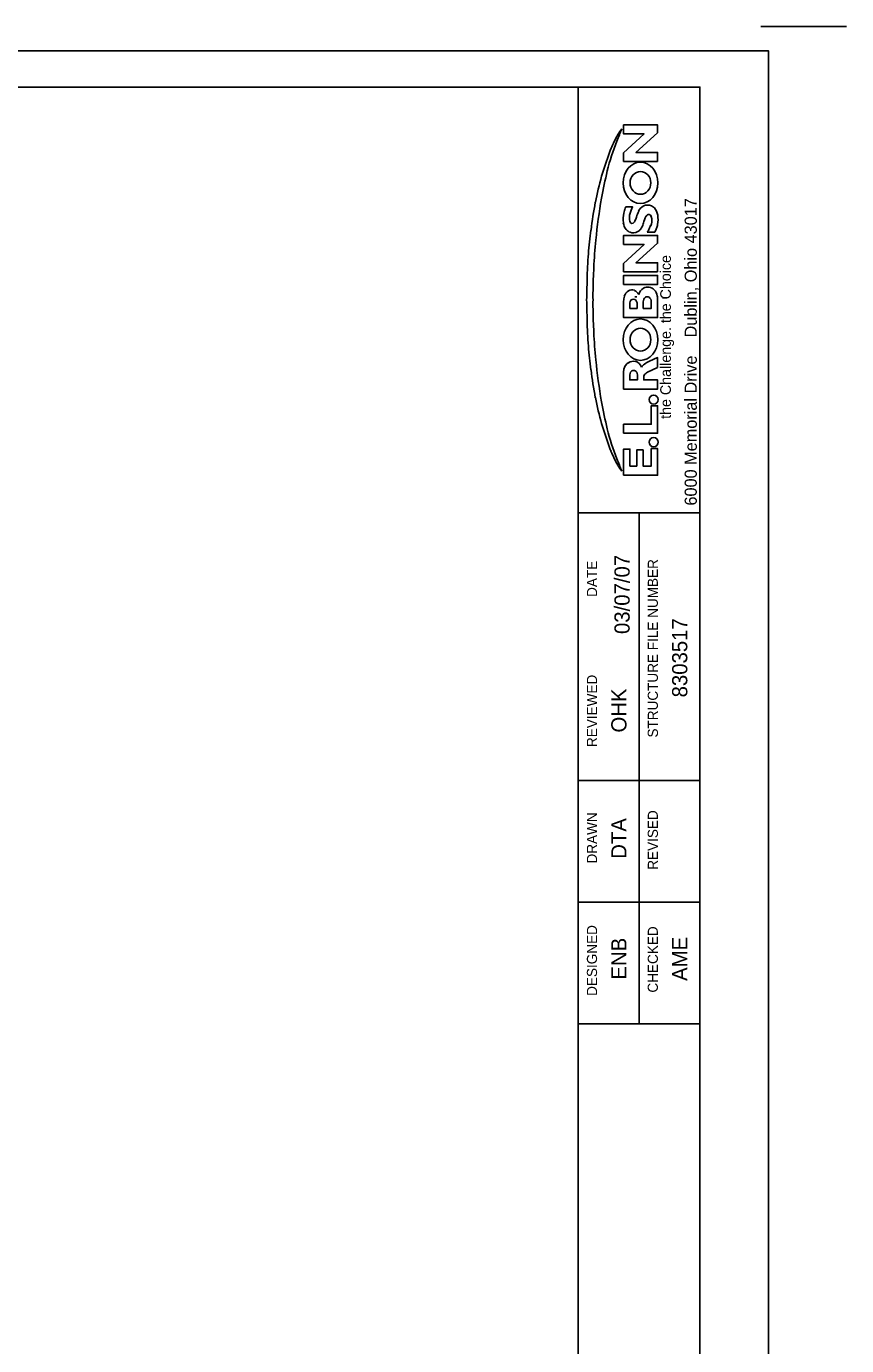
# Model space of a CAD drawing. Extents: x -9.2 to 26.7, y -24.6 to -2.6.
# Drawn here: x 20 to 26.74, y -13.46 to -2.61 of the extents above; entities that cross this region are included whole.
import ezdxf

# ---------------------------------------------------------------- set-up
doc = ezdxf.new("R2010")
doc.units = 0
for name, color, linetype in [('Default', 7, 'Continuous'), ('SH_Border', 7, 'Continuous'), ('SH_Cut_Line', 7, 'Continuous'), ('SH_Data', 7, 'Continuous')]:
    doc.layers.add(name, color=color, linetype=linetype)

msp = doc.modelspace()

# ---------------------------------------------------------------- linework, layer by layer
at = {"layer": 'Default'}
for p, q in [((25.163, -4.303), (25.101, -4.303)), ((25.101, -4.303), (25.163, -4.303)), ((24.906, -5.006), (24.906, -4.871)), ((25.185, -4.856), (25.185, -5.006)), ((24.958, -4.886), (24.958, -4.931)), ((24.958, -4.931), (24.958, -4.886)), ((25.185, -5.006), (24.906, -5.006)), ((25.185, -5.416), (25.104, -5.456)), ((25.104, -5.456), (25.185, -5.416)), ((24.957, -5.477), (24.957, -5.519)), ((24.957, -5.519), (24.957, -5.477)), ((24.957, -5.519), (25.02, -5.519)), ((25.02, -5.519), (24.957, -5.519)), ((25.02, -5.519), (25.02, -5.477)), ((25.02, -5.477), (25.02, -5.519))]:
    msp.add_line(p, q, dxfattribs=at)
for points in [[(25.185, -3.722), (24.906, -3.722), (24.906, -3.653), (25.075, -3.497), (24.906, -3.497), (24.906, -3.423), (25.185, -3.423), (25.185, -3.487), (25.008, -3.648), (25.185, -3.648)], [(25.185, -4.63), (24.906, -4.63), (24.906, -4.561), (25.075, -4.405), (24.906, -4.405), (24.906, -4.331), (25.185, -4.331), (25.185, -4.395), (25.008, -4.556), (25.185, -4.556)], [(24.906, -4.734), (24.906, -4.66), (25.185, -4.66), (25.185, -4.734)], [(24.906, -6.302), (24.906, -6.087), (24.958, -6.087), (24.958, -6.227), (25.015, -6.227), (25.015, -6.095), (25.067, -6.095), (25.067, -6.227), (25.134, -6.227), (25.134, -6.084), (25.185, -6.084), (25.185, -6.302)]]:
    msp.add_lwpolyline(points, close=True, dxfattribs=at)
for points in [[(24.924, -4.096), (24.98, -4.096), (24.969, -4.122)], [(24.969, -4.122), (24.98, -4.096), (24.924, -4.096)], [(25.185, -4.856), (25.185, -5.006), (24.906, -5.006), (24.906, -4.871)], [(24.906, -4.871), (24.906, -5.006), (25.185, -5.006)], [(25.068, -4.877), (25.068, -4.931), (25.133, -4.931), (25.133, -4.877)], [(25.133, -4.877), (25.133, -4.931), (25.068, -4.931), (25.068, -4.877)], [(25.185, -5.006), (25.185, -4.856)], [(24.958, -4.931), (25.017, -4.931), (25.017, -4.886)], [(25.017, -4.886), (25.017, -4.931), (24.958, -4.931)], [(25.12, -5.366), (25.185, -5.335), (25.185, -5.416)], [(25.185, -5.416), (25.185, -5.335), (25.12, -5.366)], [(25.072, -5.498), (25.072, -5.519), (25.185, -5.519), (25.185, -5.594), (24.906, -5.594), (24.906, -5.519), (24.906, -5.455)], [(24.906, -5.455), (24.906, -5.519), (24.906, -5.594), (25.185, -5.594)], [(24.957, -5.477), (24.957, -5.519), (25.02, -5.519), (25.02, -5.477)], [(25.185, -5.594), (25.185, -5.519), (25.072, -5.519), (25.072, -5.498)], [(24.906, -5.958), (24.906, -5.883), (25.134, -5.883), (25.134, -5.731), (25.185, -5.731), (25.185, -5.958), (24.906, -5.958)], [(25.185, -5.731), (25.134, -5.731), (25.134, -5.883), (24.906, -5.883), (24.906, -5.958)], [(24.906, -5.958), (25.185, -5.958), (25.185, -5.731)]]:
    msp.add_lwpolyline(points, dxfattribs=at)
for centre, major_axis, ratio, start_param, end_param in [((-13.595, 17.645), (0, 49.953), 0.85, 4.274094, 4.276309), ((-13.595, 17.645), (0, 49.953), 0.85, 4.274094, 4.276309), ((25.117, -3.701), (0, 0.363), 0.85, 0.822588, 0.988431), ((25.117, -3.701), (0, 0.363), 0.85, 0.822588, 0.988431), ((26.148, -4.27), (0, 1.685), 0.85, 1.132502, 1.288747), ((26.148, -4.27), (0, 1.685), 0.85, 1.132502, 1.288747), ((25.669, -4.13), (0, 1.141), 0.85, 0.988431, 1.105191), ((25.669, -4.13), (0, 1.141), 0.85, 0.988431, 1.105191), ((27.222, -4.875), (0, 3.112), 0.85, 1.165908, 1.233316), ((27.222, -4.875), (0, 3.112), 0.85, 1.165908, 1.233316), ((25.246, -3.879), (0, 0.583), 0.85, 1.105191, 1.165908), ((25.246, -3.879), (0, 0.583), 0.85, 1.105191, 1.165908), ((26.431, -4.527), (0, 2.119), 0.85, 1.243005, 1.347881), ((26.431, -4.527), (0, 2.119), 0.85, 1.243005, 1.347881), ((27.646, -4.781), (0, 3.52), 0.85, 1.288747, 1.354281), ((27.646, -4.781), (0, 3.52), 0.85, 1.288747, 1.354281), ((25.045, -3.899), (0, -0.0938), 0.910305, 4.71238898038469, 4.712389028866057), ((27.62, -4.797), (0, 3.544), 0.85, 1.360764, 1.426378), ((27.62, -4.797), (0, 3.544), 0.85, 1.360764, 1.426378), ((28.865, -4.975), (0, 4.963), 0.85, 1.378198, 1.448475), ((28.865, -4.975), (0, 4.963), 0.85, 1.378198, 1.448475), ((25.077, -4.199), (0, 0.206), 0.85, 1.108668, 1.320154), ((25.077, -4.199), (0, 0.206), 0.85, 1.108668, 1.320154), ((24.786, -4.029), (0, 0.176), 0.85, 4.250261, 4.3216), ((24.786, -4.029), (0, 0.176), 0.85, 4.250261, 4.3216), ((25.11, -4.188), (0, 0.11), 0.85, 0.486829, 1.030221), ((25.11, -4.188), (0, 0.11), 0.85, 0.486829, 1.030221), ((25.045, -3.899), (0, -0.17), 0.841969, 0, 4.84813681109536e-08), ((25.097, -4.158), (0, 0.0761), 0.85, 0.083326, 0.486829), ((25.097, -4.158), (0, 0.0761), 0.85, 0.083326, 0.486829), ((25.102, -4.236), (0, 0.154), 0.85, 6.083659, 6.366511), ((25.102, -4.236), (0, 0.154), 0.85, 6.083659, 6.366511), ((25.116, -4.158), (0, 0.0741), 0.85, 5.529173, 6.083659), ((25.116, -4.158), (0, 0.0741), 0.85, 5.529173, 6.083659), ((25.096, -4.183), (0, 0.109), 0.85, 4.887723, 5.529173), ((25.096, -4.183), (0, 0.109), 0.85, 4.887723, 5.529174), ((25.064, -4.195), (0, 0.19), 0.85, 1.320154, 1.737094), ((25.064, -4.195), (0, 0.19), 0.85, 1.320154, 1.737094), ((24.996, -4.208), (0, 0.11), 0.85, 1.737094, 2.325359), ((24.996, -4.208), (0, 0.11), 0.85, 1.737094, 2.325359), ((25.049, -4.186), (0, 0.111), 0.85, 1.456901, 1.818883), ((25.049, -4.186), (0, 0.111), 0.85, 1.456901, 1.818883), ((25.052, -4.187), (0, 0.115), 0.85, 1.297264, 1.456901), ((25.052, -4.187), (0, 0.115), 0.85, 1.297264, 1.456901), ((24.98, -4.207), (0, 0.0279), 0.85, 1.818883, 2.384672), ((24.98, -4.207), (0, 0.0279), 0.85, 1.818883, 2.384672), ((25.118, -4.209), (0, 0.196), 0.85, 1.114999, 1.297264), ((25.118, -4.209), (0, 0.196), 0.85, 1.114999, 1.297264), ((24.975, -4.213), (0, 0.0197), 0.85, 2.384672, 3.137191), ((24.975, -4.213), (0, 0.0197), 0.85, 2.384672, 3.137191), ((24.975, -4.205), (0, 0.0276), 0.85, 3.137191, 4.01614), ((24.975, -4.205), (0, 0.0276), 0.85, 3.137191, 4.01614), ((24.947, -4.177), (0, 0.071), 0.85, 4.01614, 4.175459), ((24.947, -4.177), (0, 0.071), 0.85, 4.01614, 4.175459), ((24.878, -4.129), (0, 0.165), 0.85, 4.175459, 4.396402), ((24.878, -4.129), (0, 0.165), 0.85, 4.175459, 4.396402), ((25.204, -4.254), (0, 0.238), 0.85, 1.030221, 1.254809), ((25.204, -4.254), (0, 0.238), 0.85, 1.030221, 1.254809), ((25.687, -4.508), (0, 0.778), 0.85, 1.164639, 1.211778), ((25.687, -4.508), (0, 0.778), 0.85, 1.164639, 1.211778), ((25.301, -4.312), (0, 0.284), 0.85, 1.063855, 1.164639), ((25.301, -4.312), (0, 0.284), 0.85, 1.063855, 1.164639), ((25.113, -4.19), (0, 0.0304), 0.85, 0.715581, 1.063855), ((25.113, -4.19), (0, 0.0304), 0.85, 0.715581, 1.063855), ((25.114, -4.191), (0, 0.0317), 0.85, 0.212074, 0.715581), ((25.114, -4.191), (0, 0.0317), 0.85, 0.212074, 0.715581), ((25.113, -4.185), (0, 0.026), 0.85, 5.247627, 6.495259), ((25.113, -4.185), (0, 0.026), 0.85, 5.247627, 6.495259), ((25.051, -4.205), (0, 0.103), 0.85, 4.251833, 4.86616), ((25.051, -4.205), (0, 0.103), 0.85, 4.251833, 4.86616), ((25.096, -4.196), (0, 0.0483), 0.85, 4.86616, 5.247627), ((25.096, -4.196), (0, 0.0483), 0.85, 4.86616, 5.247627), ((25.015, -4.2), (0, 0.205), 0.85, 4.51081, 4.887723), ((25.015, -4.2), (0, 0.205), 0.85, 4.51081, 4.887723), ((26.199, -4.62), (0, 1.866), 0.85, 1.391456, 1.496401), ((26.199, -4.62), (0, 1.866), 0.85, 1.391456, 1.496401), ((24.976, -4.231), (0, 0.0764), 0.85, 2.325359, 2.878408), ((24.976, -4.231), (0, 0.0764), 0.85, 2.325359, 2.878408), ((24.984, -4.196), (0, 0.113), 0.85, 2.878408, 3.55749), ((24.984, -4.196), (0, 0.113), 0.85, 2.878408, 3.55749), ((24.997, -4.232), (0, 0.0738), 0.85, 3.55749, 3.971659), ((24.997, -4.232), (0, 0.0738), 0.85, 3.55749, 3.971659), ((24.953, -4.184), (0, 0.145), 0.85, 3.971659, 4.353371), ((24.953, -4.184), (0, 0.145), 0.85, 3.971659, 4.353371), ((24.924, -4.14), (0, 0.265), 0.85, 4.050165, 4.172563), ((24.924, -4.14), (0, 0.265), 0.85, 4.050165, 4.172563), ((24.847, -4.086), (0, 0.37), 0.85, 4.172563, 4.251833), ((24.847, -4.086), (0, 0.37), 0.85, 4.172563, 4.251833), ((25.058, -4.214), (0, 0.152), 0.85, 4.087438, 4.318356), ((25.058, -4.214), (0, 0.152), 0.85, 4.087438, 4.318356), ((25.042, -4.206), (0, 0.173), 0.85, 4.318356, 4.51081), ((25.042, -4.206), (0, 0.173), 0.85, 4.318356, 4.51081), ((30.463, -5.041), (0, 6.84), 0.85, 1.472392, 1.505619), ((30.463, -5.041), (0, 6.84), 0.85, 1.472392, 1.505619), ((26.401, -4.721), (0, 2.111), 0.85, 1.456986, 1.558686), ((26.401, -4.721), (0, 2.111), 0.85, 1.456986, 1.558686), ((28.007, -4.852), (0, 3.944), 0.85, 1.505619, 1.553601), ((28.007, -4.852), (0, 3.944), 0.85, 1.505619, 1.553601), ((28.209, -4.914), (0, 4.243), 0.85, 1.519271, 1.558345), ((28.209, -4.914), (0, 4.243), 0.85, 1.519271, 1.558345), ((25.104, -4.846), (0, 0.0906), 0.85, 0.462144, 1.247207), ((25.104, -4.846), (0, 0.0906), 0.85, 0.462144, 1.247207), ((25.104, -4.846), (0, 0.0906), 0.85, 0.462144, 1.247207), ((25.105, -4.854), (0, 0.0982), 0.85, 6.14188, 6.715345), ((25.105, -4.854), (0, 0.0982), 0.85, 6.14188, 6.715345), ((25.105, -4.854), (0, 0.0982), 0.85, 6.14188, 6.715345), ((25.109, -4.845), (0, 0.0885), 0.85, 5.535543, 6.182102), ((25.109, -4.845), (0, 0.0885), 0.85, 5.535543, 6.182102), ((25.109, -4.845), (0, 0.0885), 0.85, 5.535543, 6.182102), ((28.209, -4.809), (0, 4.243), 0.85, 1.583248, 1.622322), ((28.209, -4.809), (0, 4.243), 0.85, 1.583248, 1.622322), ((26.556, -4.823), (0, 2.237), 0.85, 1.553601, 1.587991), ((26.556, -4.823), (0, 2.237), 0.85, 1.553601, 1.587991), ((26.556, -4.9), (0, 2.237), 0.85, 1.553601, 1.587991), ((26.556, -4.9), (0, 2.237), 0.85, 1.553601, 1.587991), ((25.012, -4.873), (0, 0.124), 0.85, 1.228703, 1.558605), ((25.012, -4.873), (0, 0.124), 0.85, 1.228703, 1.558605), ((25.012, -4.873), (0, 0.124), 0.85, 1.228703, 1.558605), ((24.978, -4.862), (0, 0.0833), 0.85, 0.473795, 1.194239), ((24.978, -4.862), (0, 0.0833), 0.85, 0.473795, 1.194239), ((24.978, -4.862), (0, 0.0833), 0.85, 0.473795, 1.194239), ((24.976, -4.848), (0, 0.0696), 0.85, 5.943917, 6.808987), ((24.976, -4.848), (0, 0.0696), 0.85, 5.943917, 6.808987), ((24.976, -4.848), (0, 0.0696), 0.85, 5.943917, 6.808987), ((24.986, -4.888), (0, 0.0337), 0.85, 6.249041, 7.784024), ((24.986, -4.888), (0, 0.0337), 0.85, 6.249041, 7.784024), ((24.988, -4.888), (0, 0.0337), 0.85, 4.782347, 6.317329), ((24.988, -4.888), (0, 0.0337), 0.85, 4.782347, 6.317329), ((24.974, -4.856), (0, 0.0776), 0.85, 5.231996, 5.947796), ((24.974, -4.856), (0, 0.0776), 0.85, 5.231996, 5.947796), ((24.974, -4.856), (0, 0.0776), 0.85, 5.231996, 5.947795), ((25.102, -4.875), (0, 0.0402), 0.85, 0.503186, 1.629765), ((25.102, -4.875), (0, 0.0402), 0.85, 0.503186, 1.629765), ((25.1, -4.871), (0, 0.0358), 0.85, 6.277029, 6.794667), ((25.1, -4.871), (0, 0.0358), 0.85, 6.277029, 6.794667), ((25.101, -4.871), (0, 0.0358), 0.85, 5.771704, 6.289341), ((25.101, -4.871), (0, 0.0358), 0.85, 5.771704, 6.289341), ((25.099, -4.875), (0, 0.0402), 0.85, 4.65342, 5.779999), ((25.099, -4.875), (0, 0.0402), 0.85, 4.65342, 5.779999), ((25.114, -4.841), (0, 0.0818), 0.85, 4.885157, 5.560215), ((25.114, -4.841), (0, 0.0818), 0.85, 4.885157, 5.560215), ((25.114, -4.841), (0, 0.0818), 0.85, 4.885157, 5.560215), ((25.014, -4.864), (0, 0.202), 0.85, 4.750784, 4.89449), ((25.014, -4.864), (0, 0.202), 0.85, 4.750784, 4.89449), ((25.014, -4.864), (0, 0.202), 0.85, 4.750784, 4.89449), ((28.007, -4.871), (0, 3.944), 0.85, 1.587991, 1.635974), ((28.007, -4.871), (0, 3.944), 0.85, 1.587991, 1.635974), ((26.401, -5.002), (0, 2.111), 0.85, 1.582906, 1.684607), ((26.401, -5.002), (0, 2.111), 0.85, 1.582906, 1.684607), ((30.463, -4.682), (0, 6.84), 0.85, 1.635974, 1.669201), ((30.463, -4.682), (0, 6.84), 0.85, 1.635974, 1.669201), ((25.045, -5.188), (0, -0.0938), 0.910305, 4.71238898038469, 4.712389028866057), ((26.199, -5.103), (0, 1.866), 0.85, 1.645192, 1.750137), ((26.199, -5.103), (0, 1.866), 0.85, 1.645192, 1.750137), ((28.865, -4.748), (0, 4.963), 0.85, 1.693118, 1.763395), ((28.865, -4.748), (0, 4.963), 0.85, 1.693118, 1.763395), ((24.982, -5.456), (0, 0.0895), 0.85, 0.482355, 1.561069), ((24.982, -5.456), (0, 0.0895), 0.85, 0.482355, 1.561069), ((24.988, -5.465), (0, 0.1), 0.85, 6.102437, 6.781247), ((24.988, -5.465), (0, 0.1), 0.85, 6.102437, 6.781247), ((24.987, -5.452), (0, 0.0881), 0.85, 5.152888, 6.061538), ((24.987, -5.452), (0, 0.0881), 0.85, 5.152888, 6.061538), ((25.045, -5.188), (0, -0.17), 0.841969, 0, 4.84813681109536e-08), ((25.104, -5.451), (0, 0.069), 0.85, 0.463729, 1.012038), ((25.104, -5.451), (0, 0.069), 0.85, 0.463729, 1.012038), ((25.211, -5.663), (0, 0.316), 0.85, 0.346308, 0.520291), ((25.211, -5.663), (0, 0.316), 0.85, 0.346308, 0.520291), ((27.62, -4.926), (0, 3.544), 0.85, 1.715214, 1.780828), ((27.62, -4.926), (0, 3.544), 0.85, 1.715214, 1.780828), ((24.997, -5.48), (0, 0.0467), 0.85, 1.002734, 1.50285), ((24.997, -5.48), (0, 0.0467), 0.85, 1.002734, 1.50285), ((24.997, -5.48), (0, 0.0467), 0.85, 1.002734, 1.50285), ((24.988, -5.477), (0, 0.0365), 0.85, 6.259044, 7.205975), ((24.988, -5.477), (0, 0.0365), 0.85, 6.259044, 7.205975), ((24.988, -5.477), (0, 0.0365), 0.85, 6.259044, 7.205975), ((24.989, -5.477), (0, 0.0365), 0.85, 5.360396, 6.307326), ((24.989, -5.477), (0, 0.0365), 0.85, 5.360396, 6.307326), ((24.989, -5.477), (0, 0.0365), 0.85, 5.360396, 6.307326), ((24.981, -5.48), (0, 0.0467), 0.85, 4.780335, 5.280452), ((24.981, -5.48), (0, 0.0467), 0.85, 4.780335, 5.280452), ((24.981, -5.48), (0, 0.0467), 0.85, 4.780335, 5.280452), ((25.098, -5.497), (0, 0.0303), 0.85, 0.984544, 1.600686), ((25.098, -5.497), (0, 0.0303), 0.85, 0.984544, 1.600686), ((25.121, -5.517), (0, 0.0643), 0.85, 0.32473, 0.965239), ((25.121, -5.517), (0, 0.0643), 0.85, 0.32473, 0.965239), ((26.431, -5.196), (0, 2.119), 0.85, 1.793712, 1.898588), ((26.431, -5.196), (0, 2.119), 0.85, 1.793712, 1.898588), ((27.646, -4.942), (0, 3.52), 0.85, 1.787312, 1.852845), ((27.646, -4.942), (0, 3.52), 0.85, 1.787312, 1.852845), ((25.153, -5.681), (0, -0.0377), 0.965476, 4.71238898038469, 4.712389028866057), ((27.222, -4.848), (0, 3.112), 0.85, 1.908276, 1.975684), ((27.222, -4.848), (0, 3.112), 0.85, 1.908276, 1.975684), ((26.148, -5.453), (0, 1.685), 0.85, 1.852845, 2.009091), ((26.148, -5.453), (0, 1.685), 0.85, 1.852845, 2.009091), ((25.246, -5.844), (0, 0.583), 0.85, 1.975684, 2.036401), ((25.246, -5.844), (0, 0.583), 0.85, 1.975684, 2.036401), ((25.153, -6.031), (0, -0.0377), 0.965476, 4.71238898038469, 4.712389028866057), ((25.669, -5.593), (0, 1.141), 0.85, 2.036401, 2.153161), ((25.669, -5.593), (0, 1.141), 0.85, 2.036401, 2.153161), ((-13.595, -27.368), (0, 49.953), 0.85, 5.148469, 5.150684), ((-13.595, -27.368), (0, 49.953), 0.85, 5.148469, 5.150684), ((25.117, -6.022), (0, 0.363), 0.85, 2.153161, 2.319004), ((25.117, -6.022), (0, 0.363), 0.85, 2.153161, 2.319004)]:
    msp.add_ellipse(centre, major_axis=major_axis, ratio=ratio, start_param=start_param, end_param=end_param, dxfattribs=at)
for centre, major_axis, ratio in [((25.045, -3.899), (0, -0.17), 0.841969), ((25.045, -3.899), (0, -0.17), 0.841969), ((25.045, -3.899), (0, -0.0938), 0.910305), ((25.045, -3.899), (0, -0.0938), 0.910305), ((25.045, -5.188), (0, -0.17), 0.841969), ((25.045, -5.188), (0, -0.17), 0.841969), ((25.045, -5.188), (0, -0.0938), 0.910305), ((25.045, -5.188), (0, -0.0938), 0.910305), ((25.153, -5.681), (0, -0.0377), 0.965476), ((25.153, -6.031), (0, -0.0377), 0.965476), ((25.153, -6.031), (0, -0.0377), 0.965476)]:
    msp.add_ellipse(centre, major_axis=major_axis, ratio=ratio, dxfattribs=at)
at = {"layer": 'SH_Border'}
for p, q in [((24.534, -24.112), (24.534, -3.112)), ((24.534, -6.612), (25.534, -6.612)), ((25.034, -10.812), (25.034, -6.612)), ((24.534, -8.812), (25.534, -8.812)), ((24.534, -9.812), (25.534, -9.812)), ((24.534, -10.812), (25.534, -10.812))]:
    msp.add_line(p, q, dxfattribs=at)
msp.add_lwpolyline([(-5.966, -3.112), (25.534, -3.112), (25.534, -24.112), (-5.966, -24.112)], close=True, dxfattribs=at)
at = {"layer": 'SH_Cut_Line'}
msp.add_line((26.034, -2.612), (26.739, -2.612), dxfattribs=at)
msp.add_lwpolyline([(26.096, -24.462), (-7.904, -24.462), (-7.904, -2.812), (26.096, -2.812)], close=True, dxfattribs=at)

# ---------------------------------------------------------------- texts
at = {"layer": 'Default'}
for s, height, p in [('6000 Memorial Drive    Dublin, Ohio 43017', 0.1, (25.508, -6.552)), ('the Challenge. the Choice', 0.0875, (25.295, -5.839))]:
    msp.add_text(s, height=height, rotation=90, dxfattribs=at).set_placement(p)
at = {"layer": 'SH_Data'}
for s, height, p in [('.', 0.125, (25.017, -4.859)), ("'", 0.125, (25.35, -4.859)), ('DATE', 0.0833, (24.688, -7.303)), ('03/07/07', 0.125, (24.956, -7.608)), ('STRUCTURE FILE NUMBER', 0.0833, (25.188, -8.459)), ('8303517', 0.125, (25.43, -8.129)), ('REVIEWED', 0.0833, (24.688, -8.537)), ('OHK', 0.125, (24.93, -8.418)), ('DRAWN', 0.0833, (24.688, -9.495)), ('REVISED', 0.0833, (25.188, -9.546)), ('DTA', 0.125, (24.93, -9.456)), ('DESIGNED', 0.0833, (24.688, -10.583)), ('CHECKED', 0.0833, (25.188, -10.556)), ('ENB', 0.125, (24.93, -10.449)), ('AME', 0.125, (25.43, -10.46))]:
    msp.add_text(s, height=height, rotation=90, dxfattribs=at).set_placement(p)

doc.saveas('drawing.dxf')
